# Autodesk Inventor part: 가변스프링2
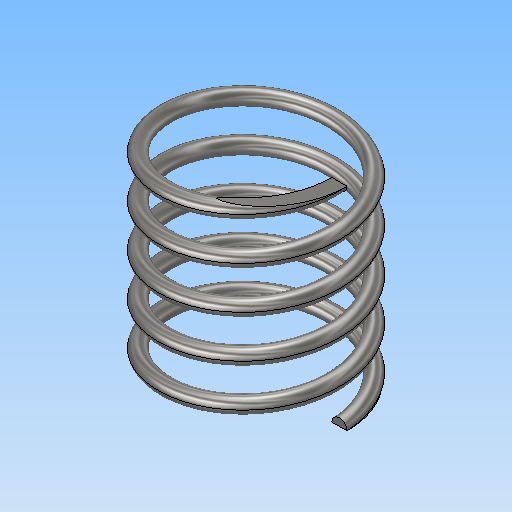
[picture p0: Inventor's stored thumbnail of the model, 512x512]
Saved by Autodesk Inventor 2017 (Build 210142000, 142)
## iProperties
Part Number: 가변스프링2
Material: 강철, 연강
Document SubType Name: Modeling
Designer: MRC
Density: 7.85 g/cm^3
Appearance: 반연마
Mass: 8.41507 g
Surface Area: 21.7061 cm^2
Volume: 1.07198 cm^3
Author: MRC
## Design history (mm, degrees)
sketch "스케치1"
  geometry: L1 (0, 0)-(0, -27.933); L2 (0, 0)-(11, 0); L3 (0, -27.933)-(11.069, -27.933); C1 r 1 at (11, 0)
  constraints: 6 end point, 2 horizontal, 1 centre point, 1 coincident, 1 vertical
  dimensions: "d1" = 22 diameter of L2.end L1; "d2" = 2 diameter of C1; "d4" = 27.93339 distance of L1.start L1.end (derived)
feature "코일1" sketch "스케치1" pitch "d5" = 10; turns "d7" = 5; dims "d6" = 27.93339 (= d4), "d8" = 0, angle "d9" = 90 deg, angle "d10" = 90 deg, "d11" = 0, "d12" = 0
sketch "스케치2"
  geometry: L1 (0, 18.659)-(-27.933, 18.659); L2 (-27.933, 18.659)-(-27.933, -18.118); L3 (-27.933, -18.118)-(0, -18.118); L4 (0, -18.118)-(0, 18.659); 1 further point
  constraints: 8 end point, 2 parallel, 1 horizontal, 1 perpendicular, 1 point on line
  dimensions: "d17" = 27.93339 distance of L2.end L3.end (= d4)
extrude "돌출1" sketch "스케치2" stored distance "d15" = 30; taper "d16" = 0 deg
node "솔리드1"
